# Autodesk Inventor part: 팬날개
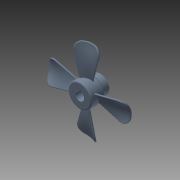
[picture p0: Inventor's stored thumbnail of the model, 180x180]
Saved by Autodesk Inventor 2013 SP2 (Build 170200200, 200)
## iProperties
Company: 한국ATC센터
Created: 2016-06
Part Number: 팬날개
Document SubType Name: Modeling
Designer: mdu
Density: 1.493 g/cm^3
Material: ABS 플라스틱
Mass: 1497.56 g
Surface Area: 466.268 cm^2
Volume: 190.529 cm^3
Author: mdu
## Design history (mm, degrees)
sketch "스케치1"
  geometry: L1 (-15, 0)-(15, 0); L2 (-15, 0)-(-15, 17); L3 (-15, 17)-(5, 17); L4 (5, 17)-(5, 13); L5 (5, 13)-(15, 13); L6 (15, 13)-(15, 0); 2 further points
  constraints: 12 end point, 3 parallel, 2 perpendicular, 1 coincident, 1 horizontal, 1 midpoint
  dimensions: "d0" = 30 distance of L1.start L1.end; "d8" = 34 diameter of L3 L1; "d10" = 26 diameter of L5 L1; "d32" = 20 distance of L2.end L3.end
revolve "회전1" sketch "스케치1" stored, may be unused: angle "d11" = 90 deg
node "작업 평면2"
sketch "스케치7"
  geometry: L1 (-15, 17)-(5, 17) reference; L2 (-15, -17)-(5, -17) reference; L3 (-5, 17)-(-5, -17); A1 r 35 centre (-36.399, -13.457) between (-2, -7) and (-8, 7); 1 further point
  constraints: 2 end point, 2 midpoint, 2 point on circle, 1 centre point
  dimensions: "d36" = 35 radius of A1; "d37" = 10 distance from line of A1.start L2; "d38" = 10 distance from line of A1.end L1; "d45" = 3 distance from line of A1.end L3; "d46" = 3 distance from line of A1.start L3
sketch "3D 스케치1"
  geometry: L1 through (0, 0) direction (1, 0) reference; L2 through (0, 0) direction (1, 0) reference; 13 other entities
  constraints: 2 collinear
  node "투영 원본 위치 스케치7"
sketch "스케치8"
  geometry: L1 (-15, 17)-(5, 17) reference; L2 (-15, -17)-(5, -17) reference; L3 (-5, 17)-(-5, -17); A1 r 30 centre (-28.74, -3.591) between (-3, -19) and (-9, 19); 1 further point
  constraints: 2 end point, 2 midpoint, 2 point on circle, 1 centre point
  dimensions: "d43" = 30 radius of A1; "d47" = 4 distance from line of A1.end L3; "d48" = 2 distance from line of A1.start L3; "d58" = 2 distance from line of A1.end L1; "d59" = 2 distance from line of A1.start L2
sketch "3D 스케치2"
sketch "3D 스케치3"
feature "경계 패치1" sketch "3D 스케치2", "3D 스케치3" dims "d50" = 0
feature "연장1" dims "d55" = 2
feature "두껍게 하기1" dims "d51" = 2, "d52" = 2
sketch "스케치9"
  geometry: C1 r 59 at (0, 0); 1 further point
  constraints: 1 centre point, 1 coincident
  dimensions: "d60" = 118 diameter of C1
extrude "돌출2" sketch "스케치9" distance "d62" = 200; taper "d63" = 0 deg
fillet "모깎기6" dims "d64" = 10
fillet "모깎기7" dims "d66" = 0.8
fillet "모깎기8" dims "d67" = 0.8
sketch "스케치2"
  geometry: L1 (-2.5, 6)-(-2.5, 8.8); L2 (-2.5, 8.8)-(2.5, 8.8); L3 (2.5, 8.8)-(2.5, 6); A1 r 6.5 centre (0, 0) between (-2.5, 6) and (2.5, 6); 1 further point
  constraints: 6 end point, 2 parallel, 2 point on circle, 1 centre point, 1 coincident, 1 horizontal, 1 vertical
  dimensions: "d12" = 13 diameter of A1; "d13" = 5 distance of L1.end L2.end; "d14" = 15.3 dimension on A1 L2 (computed from d12)
extrude "돌출1" cut sketch "스케치2" stored distance "d15" = 10; taper "d16" = 0 deg
chamfer "모따기1" distance "d17" = 1; stored, may be unused: second distance "d18" = 2, angle "d19" = 45 deg
node "작업 평면1"
sketch "스케치3"
  geometry: L1 (5, -13)-(5, 13) reference; 3 further points
  constraints: 1 horizontal alignment, 1 midpoint
  dimensions: "d20" = 5 distance from line of L1 point (0, 0)
hole "구멍1" sketch "스케치3" at (0, 0) diameter "d21" = 2.459; stored, may be unused: countersink angle "d25" = 90 deg, drill point angle "d27" = 118 deg; dims "d22" = 6, "d23" = 4, "d24" = 2, "d26" = 8
fillet "모깎기9" dims "d77" = 2
fillet "모깎기10" dims "d78" = 2
fillet "모깎기11" dims "d79" = 2
node "솔리드1"
pattern_circular "원형 패턴1" dims "d69" = 360 deg
pattern_circular "원형 패턴2" dims angle "d72" = 360 deg
pattern_circular "원형 패턴3" dims angle "d75" = 360 deg
node "투영 원본 위치 스케치8"
node "곡면1"
node "곡면2"
node "곡면3"
node "곡면4"
feature "경계 패치2"
feature "경계 패치3"
feature "경계 패치4"
